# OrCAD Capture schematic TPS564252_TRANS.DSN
size B; title: TPS564252, 3-V to 17-V input, 4-A Synchronous; rev: 1.0; note: Datasheet: SLUSEQ6     EVM: SLUUCL5; note: Synchronous Step Down Converter; note: Step-Down Voltage Regulator
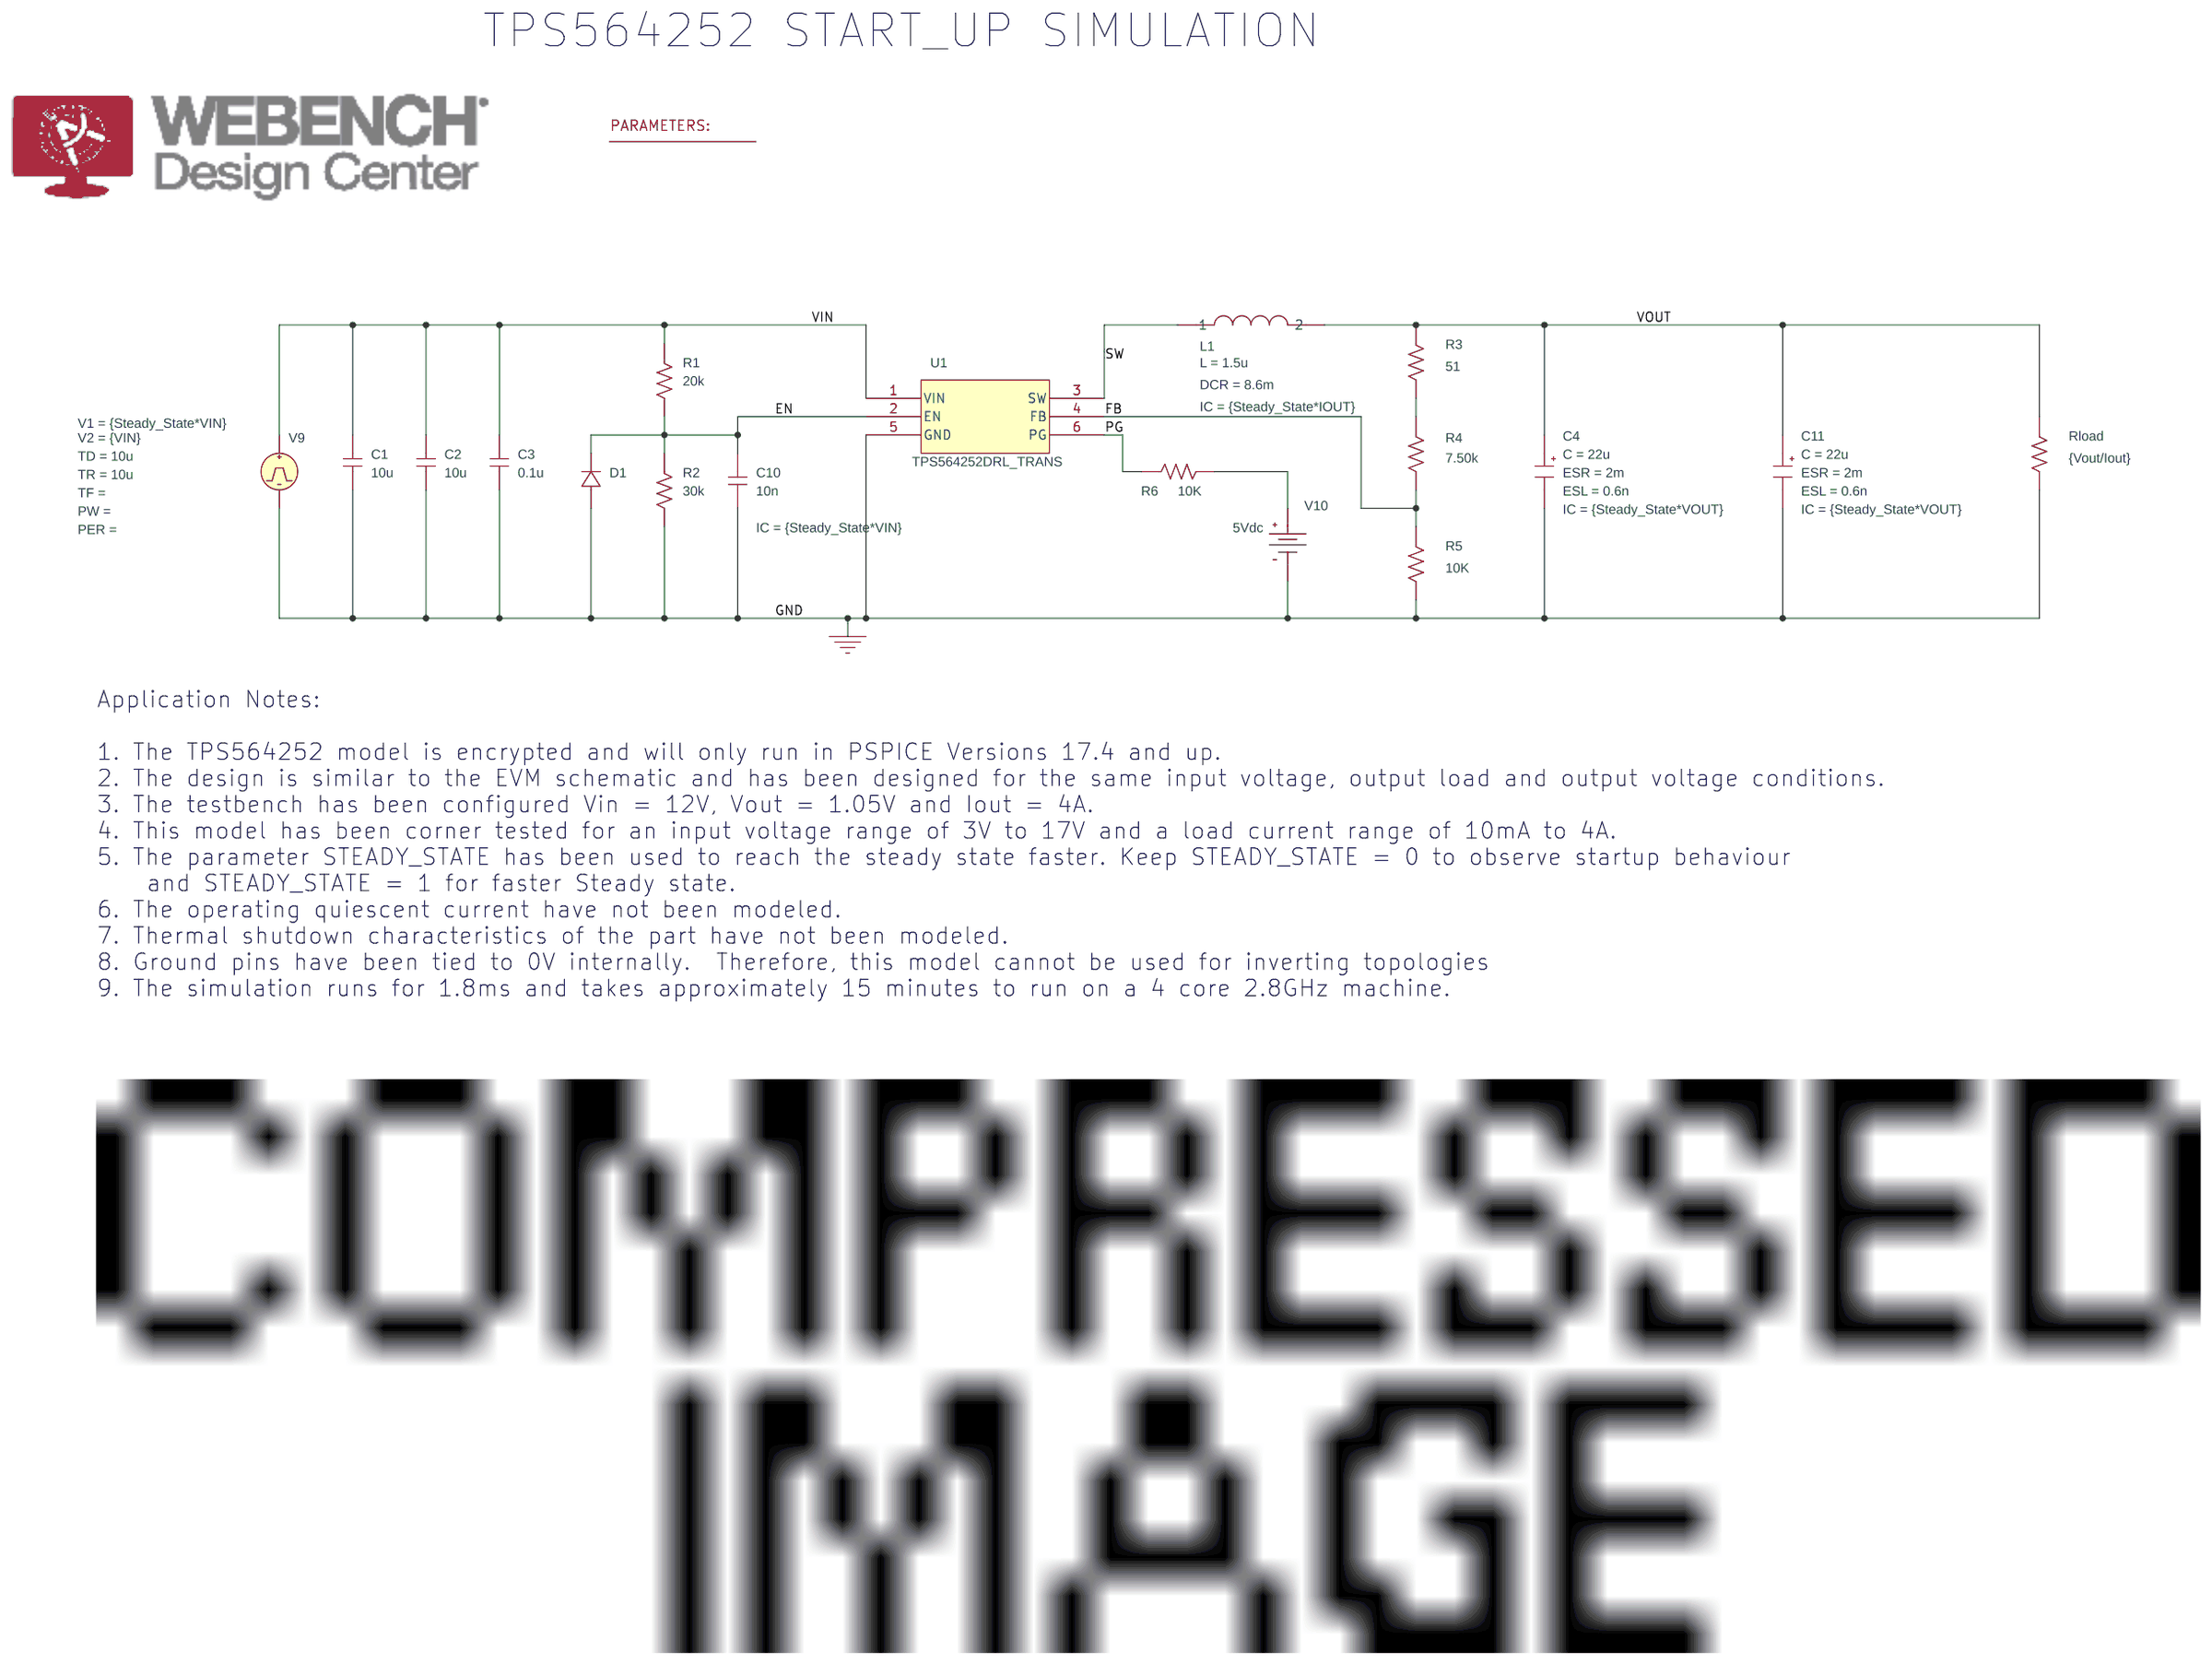
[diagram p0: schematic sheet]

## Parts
3  PARAM
C1  10u  [RAD/CK05]
C2  10u  [RAD/CK05]
C3  0.1u  [RAD/CK05]
C4  CESR
C10  10n  [RAD/CK05]
C11  CESR
D1  Dbreak
L1  LDCR
R1  20k  [AX/RC05]
R2  30k  [AX/RC05]
R3  51  [AX/RC05]
R4  7.50k  [AX/RC05]
R5  10K  [AX/RC05]
R6  10K  [AX/RC05]
Rload  {Vout/Iout}  [AX/RC05]
U1  TPS564252DRL_TRANS
V9  VPULSE
V10  VDC

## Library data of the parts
3 = PARAM: IOUT: 4; Steady_State: 0; VIN: 12; VOUT: 1.05
C1-C3 = C
C4 C11 = CESR_0: C: 22u; ESL: 0.6n; ESR: 2m; IC: {Steady_State*VOUT}
C10 = C: IC: {Steady_State*VIN}
D1 = Dbreak
L1 = LDCR: DCR: 8.6m; IC: {Steady_State*IOUT}; L: 1.5u
R1-R6 Rload = R
U1 = TPS564252_TRANS
V9 = VPULSE: TD: 10u; TR: 10u; V1: {Steady_State*VIN}; V2: {VIN}
V10 = VDC: DC: 5Vdc

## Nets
VIN: C1.1 C2.1 C3.1 R1.1 U1.1(VIN) V9.1(+)
0: C1.2 C2.2 C3.2 C4.2(OUT) C10.2 C11.2(OUT) D1.0(1) R2.2 R5.2 Rload.2 U1.5(GND) V9.2(-) V10.1(-)
EN: C10.1 D1.1(2) R1.2 R2.1 U1.2(EN)
FB: R4.2 R5.1 U1.4(FB)
PG: R6.1 U1.6(PG)
SW: L1.1 U1.3(SW)
VOUT: C4.1(IN) C11.1(IN) L1.2 R3.1 Rload.1
N25942: R3.2 R4.1
N26294: R6.2 V10.0(+)

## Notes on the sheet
- TPS564252 START_UP SIMULATION
- Application Notes:
  1. The TPS564252 model is encrypted and will only run in PSPICE Versions 17.4 and up.
  2. The design is similar to the EVM schematic and has been designed for the same input voltage, output load and output voltage conditions.
  3. The testbench has been configured Vin = 12V, Vout = 1.05V and Iout = 4A.
  4. This model has been corner tested for an input voltage range of 3V to 17V and a load current range of 10mA to 4A.
  5. The parameter STEADY_STATE has been used to reach the steady state faster. Keep STEADY_STATE = 0 to observe startup behaviour
      and STEADY_STATE = 1 for faster Steady state.
  6. The operating quiescent current have not been modeled.
  7. Thermal shutdown characteristics of the part have not been modeled.
  8. Ground pins have been tied to 0V internally.  Therefore, this model cannot be used for inverting topologies
  9. The simulation runs for 1.8ms and takes approximately 15 minutes to run on a 4 core 2.8GHz machine.
